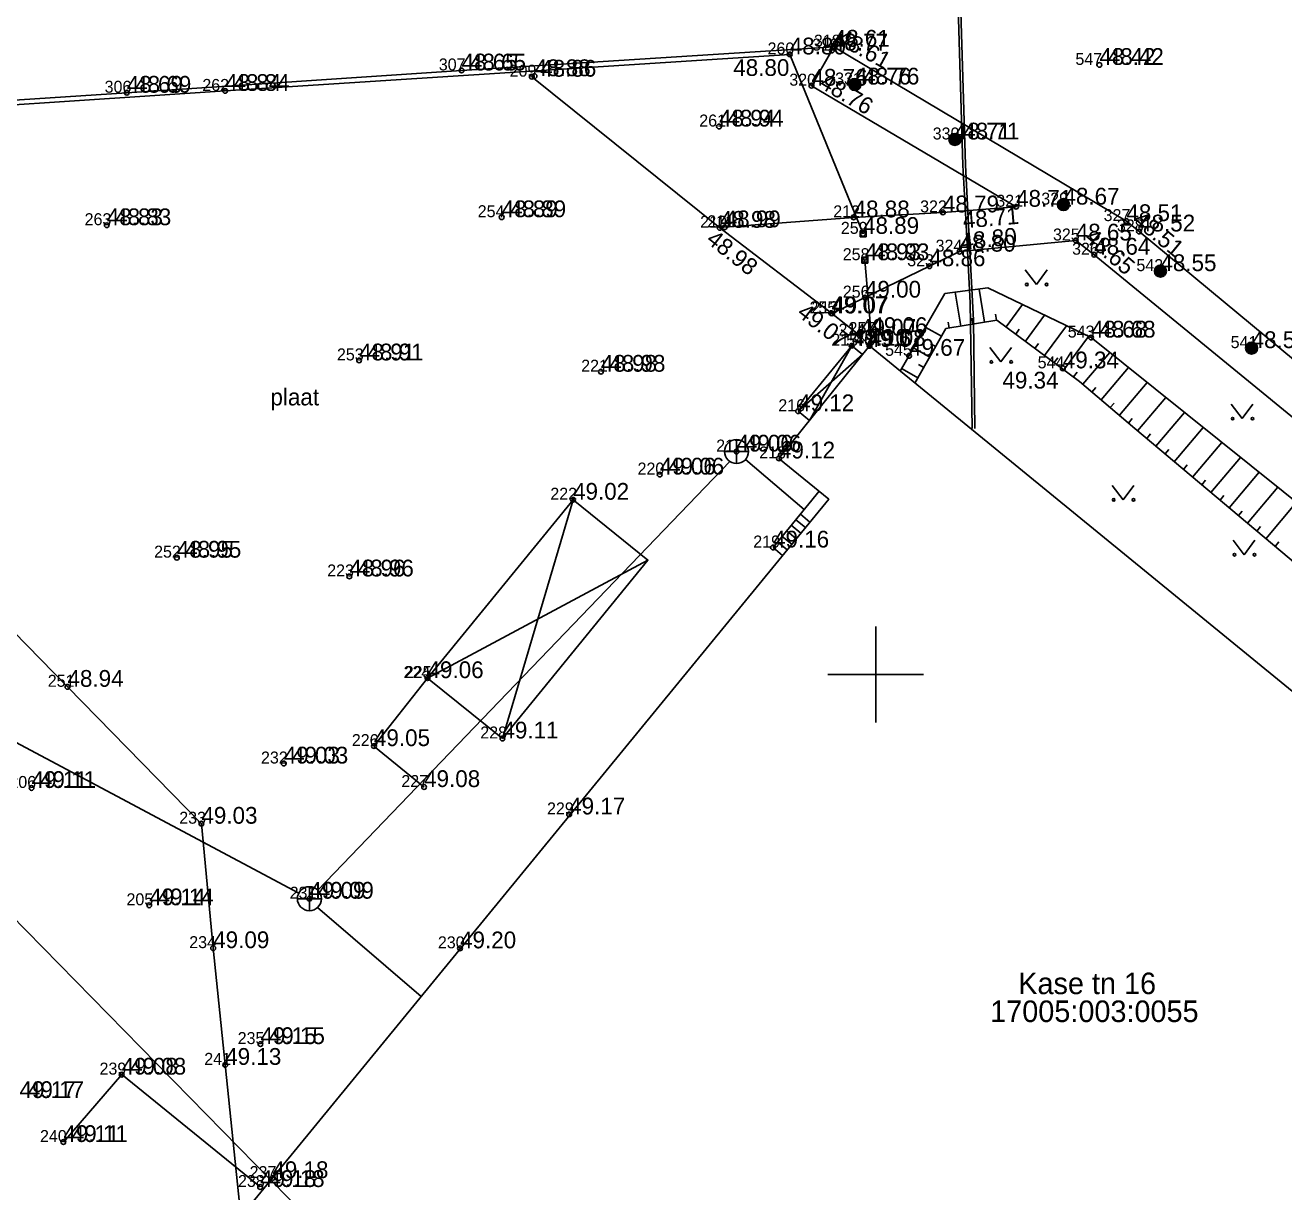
# Model space of a CAD drawing. Extents: x 640876 to 641418, y 6455595 to 6456085.
# Drawn here: x 641114.5 to 641167, y 6455928.4 to 6455977.1 of the extents above; entities that cross this region are included whole.
import ezdxf

# ---------------------------------------------------------------- set-up
doc = ezdxf.new("R2010")
doc.units = 0
for name, color, linetype in [('AED', 7, 'Continuous'), ('HALJASTUS', 7, 'Continuous'), ('HOONE', 7, 'Continuous'), ('HOONEDET', 7, 'Continuous'), ('KKAEV', 7, 'Continuous'), ('KORGUS', 7, 'Continuous'), ('KTRASS', 7, 'Continuous'), ('MOOTKORG', 7, 'Continuous'), ('MOOTMPUNKT', 7, 'Continuous'), ('MOOTNR', 7, 'Continuous'), ('MPKAABEL', 7, 'Continuous'), ('PIIR', 7, 'Continuous'), ('RAJATIS', 7, 'Continuous'), ('RELJEEF', 7, 'Continuous'), ('TEE', 7, 'Continuous'), ('VORK', 7, 'Continuous')]:
    doc.layers.add(name, color=color, linetype=linetype)

msp = doc.modelspace()

# ---------------------------------------------------------------- linework, layer by layer
at = {"layer": 'AED'}
for p, q in [((641149.345, 6455968.521), (641149.345, 6455968.271)), ((641149.345, 6455968.521), (641149.595, 6455968.521)), ((641149.345, 6455968.271), (641149.595, 6455968.271)), ((641149.595, 6455968.521), (641149.595, 6455968.271)), ((641149.424, 6455967.422), (641149.424, 6455967.172)), ((641149.424, 6455967.422), (641149.674, 6455967.422)), ((641149.424, 6455967.172), (641149.674, 6455967.172)), ((641149.674, 6455967.422), (641149.674, 6455967.172))]:
    msp.add_line(p, q, dxfattribs=at)
for points in [[(641149.47, 6455968.396), (641146.41, 6455975.887), (641122.837, 6455974.363), (641106.897, 6455973.309), (641093.89, 6455972.505), (641088.371, 6455978.142)], [(641149.742, 6455963.717), (641149.817, 6455964.213), (641149.549, 6455967.297)], [(641131.288, 6455949.849), (641129.051, 6455947.011), (641131.145, 6455945.301)], [(641124.299, 6455928.604), (641118.519, 6455933.296), (641116.084, 6455930.482)]]:
    msp.add_lwpolyline(points, dxfattribs=at)
at = {"layer": 'HALJASTUS'}
for p, q in [((641156.245, 6455966.89), (641156.709, 6455966.283)), ((641156.709, 6455966.283), (641157.154, 6455966.89)), ((641154.766, 6455963.656), (641155.23, 6455963.049)), ((641155.23, 6455963.049), (641155.675, 6455963.656)), ((641164.841, 6455961.288), (641165.304, 6455960.681)), ((641165.304, 6455960.681), (641165.75, 6455961.288)), ((641159.873, 6455957.895), (641160.336, 6455957.288)), ((641160.336, 6455957.288), (641160.782, 6455957.895)), ((641164.92, 6455955.607), (641165.383, 6455955)), ((641165.383, 6455955), (641165.829, 6455955.607))]:
    msp.add_line(p, q, dxfattribs=at)
for centre in [(641156.308, 6455966.283), (641157.136, 6455966.283), (641154.829, 6455963.049), (641155.657, 6455963.049), (641164.903, 6455960.681), (641165.732, 6455960.681), (641159.935, 6455957.288), (641160.764, 6455957.288), (641164.982, 6455955), (641165.811, 6455955)]:
    msp.add_circle(centre, 0.055, dxfattribs=at)
at = {"layer": 'HOONE'}
for p, q in [((641149.452, 6455963.357), (641148.998, 6455963.723)), ((641147.238, 6455960.606), (641146.76, 6455960.991))]:
    msp.add_line(p, q, dxfattribs=at)
for points in [[(641119.462, 6455922.449), (641148.038, 6455957.319), (641145.961, 6455959.02), (641149.742, 6455963.717)], [(641146.76, 6455960.991), (641148.998, 6455963.723)], [(641149.742, 6455963.717), (641189.36, 6455931.349)], [(641131.288, 6455949.849), (641140.492, 6455954.775), (641137.364, 6455957.296), (641131.288, 6455949.849), (641134.415, 6455947.328)], [(641140.492, 6455954.775), (641134.415, 6455947.328), (641137.364, 6455957.296)]]:
    msp.add_lwpolyline(points, dxfattribs=at)
at = {"layer": 'HOONEDET'}
for p, q in [((641147.637, 6455957.647), (641145.714, 6455955.301)), ((641147.256, 6455956.365), (641146.855, 6455956.693)), ((641146.685, 6455955.669), (641146.284, 6455955.997)), ((641146.875, 6455955.901), (641146.474, 6455956.229)), ((641147.065, 6455956.133), (641146.665, 6455956.461)), ((641146.305, 6455955.204), (641145.904, 6455955.533)), ((641146.495, 6455955.437), (641146.094, 6455955.765)), ((641146.115, 6455954.972), (641145.714, 6455955.301))]:
    msp.add_line(p, q, dxfattribs=at)
for points in [[(641146.76, 6455960.991), (641149.452, 6455963.357)], [(641148.998, 6455963.723), (641147.238, 6455960.606)]]:
    msp.add_lwpolyline(points, dxfattribs=at)
at = {"layer": 'KKAEV'}
for p, q in [((641144.191, 6455958.807), (641144.191, 6455959.807)), ((641143.691, 6455959.307), (641144.691, 6455959.307)), ((641126.355, 6455940.14), (641126.355, 6455941.14)), ((641125.855, 6455940.64), (641126.855, 6455940.64))]:
    msp.add_line(p, q, dxfattribs=at)
for centre in [(641144.191, 6455959.307), (641126.355, 6455940.64)]:
    msp.add_circle(centre, 0.5, dxfattribs=at)
at = {"layer": 'KORGUS'}
for centre in [(641146.41, 6455975.887), (641148.246, 6455976.21), (641159.338, 6455975.449), (641132.709, 6455975.218), (641135.642, 6455974.958), (641118.732, 6455974.289), (641122.837, 6455974.363), (641147.318, 6455974.582), (641149.131, 6455974.631), (641143.459, 6455972.877), (641153.305, 6455972.336), (641155.86, 6455969.527), (641134.384, 6455969.091), (641117.897, 6455968.757), (641143.492, 6455968.649), (641160.465, 6455968.928), (641158.352, 6455968.119), (641153.501, 6455967.653), (641149.549, 6455967.297), (641148.148, 6455965.083), (641158.993, 6455964.066), (641151.393, 6455963.305), (641128.431, 6455963.113), (641157.811, 6455962.781), (641138.528, 6455962.641), (641144.191, 6455959.307), (641140.982, 6455958.347), (641120.822, 6455954.878), (641128.024, 6455954.094), (641125.286, 6455946.284), (641114.756, 6455945.263), (641126.355, 6455940.64), (641119.67, 6455940.365), (641124.312, 6455934.571), (641118.519, 6455933.296), (641116.084, 6455930.482), (641124.299, 6455928.604)]:
    msp.add_circle(centre, 0.1, dxfattribs=at)
at = {"layer": 'KTRASS'}
for points in [[(641126.705, 6455940.99), (641143.906, 6455958.896)], [(641144.564, 6455958.974), (641147.015, 6455956.889)], [(641107.541, 6455950.658), (641125.909, 6455940.865)], [(641126.693, 6455940.271), (641131.028, 6455936.563)]]:
    msp.add_lwpolyline(points, dxfattribs=at)
at = {"layer": 'MOOTMPUNKT'}
for centre in [(641146.41, 6455975.887), (641148.17, 6455976.048), (641148.246, 6455976.21), (641159.338, 6455975.449), (641132.709, 6455975.218), (641135.642, 6455974.958), (641135.757, 6455974.98), (641118.732, 6455974.289), (641122.837, 6455974.363), (641147.318, 6455974.582), (641149.131, 6455974.631), (641143.459, 6455972.877), (641153.305, 6455972.336), (641155.86, 6455969.527), (641157.838, 6455969.617), (641134.384, 6455969.091), (641149.077, 6455969.085), (641152.805, 6455969.293), (641117.897, 6455968.757), (641143.492, 6455968.649), (641143.695, 6455968.671), (641160.465, 6455968.928), (641160.995, 6455968.496), (641149.47, 6455968.396), (641158.352, 6455968.119), (641153.501, 6455967.653), (641159.124, 6455967.526), (641149.549, 6455967.297), (641152.24, 6455967.045), (641161.885, 6455966.84), (641149.551, 6455965.734), (641148.148, 6455965.083), (641148.186, 6455965.074), (641148.998, 6455963.723), (641149.347, 6455964.145), (641149.817, 6455964.213), (641158.993, 6455964.066), (641149.742, 6455963.717), (641151.393, 6455963.305), (641165.694, 6455963.626), (641128.431, 6455963.113), (641157.811, 6455962.781), (641138.528, 6455962.641), (641146.76, 6455960.991), (641144.191, 6455959.307), (641145.961, 6455959.02), (641140.982, 6455958.347), (641137.364, 6455957.296), (641120.822, 6455954.878), (641145.714, 6455955.301), (641128.024, 6455954.094), (641131.288, 6455949.849), (641131.288, 6455949.849), (641116.257, 6455949.486), (641129.051, 6455947.011), (641134.415, 6455947.328), (641125.286, 6455946.284), (641114.756, 6455945.263), (641131.145, 6455945.301), (641121.847, 6455943.77), (641137.202, 6455944.159), (641126.355, 6455940.64), (641119.67, 6455940.365), (641122.34, 6455938.576), (641132.646, 6455938.568), (641124.312, 6455934.571), (641118.519, 6455933.296), (641122.842, 6455933.704), (641116.084, 6455930.482), (641124.299, 6455928.604), (641124.81, 6455928.975)]:
    msp.add_circle(centre, 0.1, dxfattribs=at)
at = {"layer": 'MPKAABEL'}
for points in [[(641081.282, 6455986.001), (641083.826, 6455989.191), (641093.656, 6455990.177), (641101.434, 6455990.689), (641109.211, 6455991.201), (641116.735, 6455992.286), (641117.253, 6455992.438), (641137.02, 6455993.508), (641152.446, 6455994.375), (641152.745, 6455994.399), (641153.077, 6455993.956), (641153.192, 6455989.529), (641153.743, 6455971.272), (641153.877, 6455968.765), (641154.087, 6455964.787), (641154.134, 6455960.265)], [(641154.034, 6455960.264), (641153.95, 6455965.518), (641153.778, 6455968.761), (641153.643, 6455971.268), (641153.102, 6455989.126), (641152.978, 6455993.905), (641152.599, 6455994.224), (641152.147, 6455994.252), (641142.791, 6455993.73), (641131.26, 6455993.087), (641117.217, 6455992.367), (641116.76, 6455992.188), (641112.991, 6455991.645), (641109.221, 6455991.101), (641101.443, 6455990.589), (641093.665, 6455990.077), (641088.757, 6455989.569), (641083.848, 6455989.06), (641081.36, 6455985.939)]]:
    msp.add_lwpolyline(points, dxfattribs=at)
at = {"layer": 'PIIR'}
for points in [[(641222.58, 6455998.61), (641237.36, 6455995.24), (641235.34, 6455991.29), (641228.11, 6455971.68), (641220.5, 6455953.19), (641213.41, 6455936.25), (641201.58, 6455908.74), (641224.93, 6455905.88), (641191.87, 6455860.58), (641157.02, 6455885.66), (641160.91, 6455891.99), (641102.26, 6455951.82), (641074.95, 6455979.64), (641084.84, 6455991.92)], [(641098.62, 6455818.85), (641093.41, 6455823.22), (641084.65, 6455830.08), (641067.32, 6455843.61), (641055.55, 6455852.8), (641061.31, 6455859.9), (641051.68, 6455867.61), (641067, 6455888.54), (641060.97, 6455894.57), (641075.14, 6455914.24), (641087.11, 6455930.82), (641102.26, 6455951.82), (641160.91, 6455891.99), (641157.02, 6455885.66), (641139.49, 6455869), (641124.05, 6455849.81)]]:
    msp.add_lwpolyline(points, close=True, dxfattribs=at)
at = {"layer": 'RAJATIS'}
for centre, radius in [((641149.131, 6455974.631), 0.25), ((641149.131, 6455974.631), 0.225), ((641149.131, 6455974.631), 0.2), ((641149.131, 6455974.631), 0.175), ((641149.131, 6455974.631), 0.15), ((641149.131, 6455974.631), 0.125), ((641149.131, 6455974.631), 0.1), ((641149.131, 6455974.631), 0.075), ((641149.131, 6455974.631), 0.05), ((641149.131, 6455974.631), 0.025), ((641153.305, 6455972.336), 0.25), ((641153.305, 6455972.336), 0.225), ((641153.305, 6455972.336), 0.2), ((641153.305, 6455972.336), 0.175), ((641153.305, 6455972.336), 0.15), ((641153.305, 6455972.336), 0.125), ((641153.305, 6455972.336), 0.1), ((641153.305, 6455972.336), 0.075), ((641153.305, 6455972.336), 0.05), ((641153.305, 6455972.336), 0.025), ((641157.838, 6455969.617), 0.25), ((641157.838, 6455969.617), 0.225), ((641157.838, 6455969.617), 0.2), ((641157.838, 6455969.617), 0.175), ((641157.838, 6455969.617), 0.15), ((641157.838, 6455969.617), 0.125), ((641157.838, 6455969.617), 0.1), ((641157.838, 6455969.617), 0.075), ((641157.838, 6455969.617), 0.05), ((641157.838, 6455969.617), 0.025), ((641161.885, 6455966.84), 0.25), ((641161.885, 6455966.84), 0.225), ((641161.885, 6455966.84), 0.2), ((641161.885, 6455966.84), 0.175), ((641161.885, 6455966.84), 0.15), ((641161.885, 6455966.84), 0.125), ((641161.885, 6455966.84), 0.1), ((641161.885, 6455966.84), 0.075), ((641161.885, 6455966.84), 0.05), ((641161.885, 6455966.84), 0.025), ((641165.694, 6455963.626), 0.25), ((641165.694, 6455963.626), 0.225), ((641165.694, 6455963.626), 0.2), ((641165.694, 6455963.626), 0.175), ((641165.694, 6455963.626), 0.15), ((641165.694, 6455963.626), 0.125), ((641165.694, 6455963.626), 0.1), ((641165.694, 6455963.626), 0.075), ((641165.694, 6455963.626), 0.05), ((641165.694, 6455963.626), 0.025)]:
    msp.add_circle(centre, radius, dxfattribs=at)
at = {"layer": 'RELJEEF'}
for p, q in [((641153.559, 6455964.543), (641153.321, 6455965.959)), ((641154.545, 6455964.709), (641154.313, 6455966.09)), ((641155.443, 6455964.508), (641156.134, 6455965.441)), ((641154.052, 6455964.626), (641154.011, 6455964.873)), ((641155.038, 6455964.792), (641154.997, 6455965.038)), ((641156.247, 6455963.913), (641157.051, 6455964.999)), ((641152.751, 6455964.122), (641152.099, 6455964.493)), ((641153.066, 6455964.461), (641153.024, 6455964.707)), ((641155.845, 6455964.21), (641155.994, 6455964.411)), ((641157.051, 6455963.318), (641157.969, 6455964.558)), ((641157.854, 6455962.723), (641158.886, 6455964.117)), ((641152.257, 6455963.253), (641151.605, 6455963.624)), ((641152.504, 6455963.688), (641152.287, 6455963.811)), ((641156.649, 6455963.615), (641156.798, 6455963.816)), ((641158.65, 6455962.118), (641159.776, 6455963.438)), ((641152.01, 6455962.818), (641151.793, 6455962.942)), ((641157.453, 6455963.02), (641157.601, 6455963.221)), ((641159.411, 6455961.469), (641160.557, 6455962.812)), ((641151.763, 6455962.384), (641151.111, 6455962.754)), ((641158.256, 6455962.425), (641158.405, 6455962.626)), ((641159.03, 6455961.793), (641159.193, 6455961.983)), ((641160.172, 6455960.82), (641161.337, 6455962.186)), ((641159.791, 6455961.144), (641159.953, 6455961.334)), ((641160.933, 6455960.172), (641162.107, 6455961.569)), ((641160.552, 6455960.495), (641160.714, 6455960.685)), ((641161.699, 6455959.528), (641162.887, 6455960.943)), ((641162.464, 6455958.885), (641163.668, 6455960.317)), ((641161.316, 6455959.85), (641161.477, 6455960.041)), ((641163.23, 6455958.242), (641164.448, 6455959.691)), ((641162.082, 6455959.207), (641162.242, 6455959.398)), ((641162.847, 6455958.563), (641163.008, 6455958.755)), ((641163.996, 6455957.598), (641165.229, 6455959.066)), ((641163.613, 6455957.92), (641163.774, 6455958.111)), ((641164.761, 6455956.955), (641166.009, 6455958.44)), ((641165.527, 6455956.312), (641166.789, 6455957.814)), ((641164.378, 6455957.277), (641164.539, 6455957.468)), ((641166.292, 6455955.669), (641167.57, 6455957.189)), ((641165.144, 6455956.633), (641165.305, 6455956.825)), ((641165.91, 6455955.99), (641166.07, 6455956.182)), ((641166.675, 6455955.347), (641166.836, 6455955.538))]:
    msp.add_line(p, q, dxfattribs=at)
for points in [[(641151.026, 6455962.667), (641152.889, 6455965.903), (641154.684, 6455966.138), (641158.993, 6455964.066), (641177.637, 6455949.117), (641191.912, 6455936.582), (641192.954, 6455935.439), (641193.346, 6455934.637), (641193.426, 6455931.281), (641192.589, 6455929.191), (641189.209, 6455924.627), (641185.194, 6455919.704), (641183.118, 6455916.876)], [(641151.64, 6455962.166), (641152.931, 6455964.438), (641155.056, 6455964.795), (641158.507, 6455962.239), (641160.822, 6455960.264), (641191.133, 6455934.798)]]:
    msp.add_lwpolyline(points, dxfattribs=at)
at = {"layer": 'TEE'}
for points in [[(641219.562, 6455985.852), (641216.822, 6455976.794), (641214.309, 6455968.346), (641210.175, 6455958.541), (641206.979, 6455950.86), (641202.453, 6455940.169), (641200.572, 6455935.729), (641195.267, 6455940.101), (641183.381, 6455949.957), (641172.174, 6455959.233), (641160.995, 6455968.496)], [(641088.438, 6455978.34), (641093.974, 6455972.705), (641102.503, 6455973.228), (641118.732, 6455974.289), (641132.709, 6455975.218), (641148.246, 6455976.21), (641160.465, 6455968.928), (641160.995, 6455968.496)], [(641148.17, 6455976.048), (641147.318, 6455974.582), (641155.86, 6455969.527), (641152.805, 6455969.293), (641149.077, 6455969.085)], [(641135.642, 6455974.958), (641143.492, 6455968.649), (641148.148, 6455965.083), (641149.347, 6455964.145), (641149.742, 6455963.717)], [(641123.495, 6455927.37), (641122.34, 6455938.576), (641121.847, 6455943.77), (641116.257, 6455949.486), (641107.796, 6455958.136), (641098.01, 6455968.023), (641093.89, 6455972.505)], [(641143.484, 6455968.655), (641149.077, 6455969.085)], [(641149.551, 6455965.734), (641152.24, 6455967.045), (641153.501, 6455967.653), (641158.352, 6455968.119), (641159.124, 6455967.526), (641170.932, 6455957.845)], [(641148.186, 6455965.074), (641149.551, 6455965.734)]]:
    msp.add_lwpolyline(points, dxfattribs=at)
at = {"layer": 'VORK'}
for p, q in [((641150, 6455952), (641150, 6455948)), ((641148, 6455950), (641152, 6455950))]:
    msp.add_line(p, q, dxfattribs=at)

# ---------------------------------------------------------------- texts
at = {"layer": 'KORGUS'}
for s, rotation, p in [('48.61', 331.5359, (641148.318, 6455976.371)), ('48.76', 329.4133, (641147.605, 6455974.532)), ('48.71', 4.7785, (641153.665, 6455968.621)), ('48.51', 320.3826, (641160.69, 6455968.883)), ('48.80', 6.0406, (641153.602, 6455967.721)), ('48.98', 321.6919, (641142.88, 6455968.067)), ('48.65', 319.3834, (641158.661, 6455968.155)), ('49.07', 322.4862, (641146.673, 6455965.005))]:
    msp.add_text(s, height=0.7, rotation=rotation, dxfattribs=at).set_placement(p)
for s, p in [('48.65', (641133.059, 6455975.218)), ('48.42', (641159.688, 6455975.449)), ('48.86', (641135.992, 6455974.958)), ('48.80', (641144.053, 6455974.989)), ('48.69', (641119.082, 6455974.289)), ('48.84', (641123.187, 6455974.363)), ('48.76', (641149.481, 6455974.631)), ('48.94', (641143.809, 6455972.877)), ('48.71', (641153.655, 6455972.336)), ('48.89', (641134.734, 6455969.091)), ('48.83', (641118.247, 6455968.757)), ('48.93', (641149.899, 6455967.297)), ('49.67', (641149.658, 6455963.675)), ('48.68', (641159.343, 6455964.066)), ('48.91', (641128.781, 6455963.113)), ('48.98', (641138.878, 6455962.641)), ('49.34', (641155.29, 6455961.938)), ('49.06', (641144.541, 6455959.307)), ('49.06', (641141.332, 6455958.347)), ('48.95', (641121.172, 6455954.878)), ('48.96', (641128.374, 6455954.094)), ('49.03', (641125.636, 6455946.284)), ('49.11', (641115.106, 6455945.263)), ('49.09', (641126.705, 6455940.64)), ('49.14', (641120.02, 6455940.365)), ('49.15', (641124.662, 6455934.571)), ('49.08', (641118.869, 6455933.296)), ('49.17', (641114.604, 6455932.318)), ('49.11', (641116.434, 6455930.482)), ('49.18', (641124.649, 6455928.604))]:
    msp.add_text(s, height=0.7, dxfattribs=at).set_placement(p)
at = {"layer": 'MOOTKORG'}
for s, p in [('48.80', (641146.41, 6455975.887)), ('48.77', (641148.17, 6455976.048)), ('48.61', (641148.246, 6455976.21)), ('48.65', (641132.709, 6455975.218)), ('48.42', (641159.338, 6455975.449)), ('48.88', (641135.757, 6455974.98)), ('48.69', (641118.732, 6455974.289)), ('48.84', (641122.837, 6455974.363)), ('48.76', (641147.318, 6455974.582)), ('48.76', (641149.131, 6455974.631)), ('48.94', (641143.459, 6455972.877)), ('48.71', (641153.305, 6455972.336)), ('48.71', (641155.86, 6455969.527)), ('48.67', (641157.838, 6455969.617)), ('48.89', (641134.384, 6455969.091)), ('48.88', (641149.077, 6455969.085)), ('48.79', (641152.805, 6455969.293)), ('48.51', (641160.465, 6455968.928)), ('48.83', (641117.897, 6455968.757)), ('48.98', (641143.492, 6455968.649)), ('48.99', (641143.695, 6455968.671)), ('48.89', (641149.47, 6455968.396)), ('48.52', (641160.995, 6455968.496)), ('48.65', (641158.352, 6455968.119)), ('48.80', (641153.501, 6455967.653)), ('48.64', (641159.124, 6455967.526)), ('48.93', (641149.549, 6455967.297)), ('48.86', (641152.24, 6455967.045)), ('48.55', (641161.885, 6455966.84)), ('49.00', (641149.551, 6455965.734)), ('49.07', (641148.148, 6455965.083)), ('49.07', (641148.186, 6455965.074)), ('49.06', (641149.817, 6455964.213)), ('49.10', (641148.998, 6455963.723)), ('49.07', (641149.347, 6455964.145)), ('49.08', (641149.742, 6455963.717)), ('48.68', (641158.993, 6455964.066)), ('48.91', (641128.431, 6455963.113)), ('49.67', (641151.393, 6455963.305)), ('48.54', (641165.694, 6455963.626)), ('48.98', (641138.528, 6455962.641)), ('49.34', (641157.811, 6455962.781)), ('49.12', (641146.76, 6455960.991)), ('49.06', (641144.191, 6455959.307)), ('49.12', (641145.961, 6455959.02)), ('49.06', (641140.982, 6455958.347)), ('49.02', (641137.364, 6455957.296)), ('49.16', (641145.714, 6455955.301)), ('48.95', (641120.822, 6455954.878)), ('48.96', (641128.024, 6455954.094)), ('48.94', (641116.257, 6455949.486)), ('49.06', (641131.288, 6455949.849)), ('49.06', (641131.288, 6455949.849)), ('49.05', (641129.051, 6455947.011)), ('49.11', (641134.415, 6455947.328)), ('49.03', (641125.286, 6455946.284)), ('49.11', (641114.756, 6455945.263)), ('49.08', (641131.145, 6455945.301)), ('49.03', (641121.847, 6455943.77)), ('49.17', (641137.202, 6455944.159)), ('49.09', (641126.355, 6455940.64)), ('49.14', (641119.67, 6455940.365)), ('49.09', (641122.34, 6455938.576)), ('49.20', (641132.646, 6455938.568)), ('49.15', (641124.312, 6455934.571)), ('49.13', (641122.842, 6455933.704)), ('49.08', (641118.519, 6455933.296)), ('49.17', (641114.254, 6455932.318)), ('49.11', (641116.084, 6455930.482)), ('49.18', (641124.81, 6455928.975)), ('49.18', (641124.299, 6455928.604))]:
    msp.add_text(s, height=0.7, dxfattribs=at).set_placement(p)
at = {"layer": 'MOOTNR'}
for s, p in [('319', (641147.345, 6455976.048)), ('318', (641147.421, 6455976.21)), ('260', (641145.485, 6455975.887)), ('547', (641158.338, 6455975.449)), ('307', (641131.759, 6455975.218)), ('209', (641134.717, 6455974.958)), ('262', (641121.887, 6455974.363)), ('320', (641146.393, 6455974.582)), ('331', (641148.306, 6455974.631)), ('306', (641117.807, 6455974.289)), ('261', (641142.634, 6455972.877)), ('330', (641152.38, 6455972.336)), ('322', (641151.855, 6455969.293)), ('321', (641155.035, 6455969.527)), ('329', (641156.913, 6455969.617)), ('263', (641116.972, 6455968.757)), ('254', (641133.384, 6455969.091)), ('210', (641142.668, 6455968.649)), ('211', (641142.97, 6455968.671)), ('212', (641148.227, 6455969.085)), ('327', (641159.515, 6455968.928)), ('259', (641148.545, 6455968.396)), ('325', (641157.402, 6455968.119)), ('328', (641160.07, 6455968.496)), ('324', (641152.501, 6455967.653)), ('326', (641158.199, 6455967.526)), ('258', (641148.624, 6455967.297)), ('323', (641151.315, 6455967.045)), ('542', (641160.885, 6455966.84)), ('256', (641148.626, 6455965.734)), ('255', (641147.236, 6455965.074)), ('213', (641147.323, 6455965.083)), ('214', (641148.447, 6455964.145)), ('257', (641148.867, 6455964.213)), ('543', (641158.018, 6455964.066)), ('215', (641148.148, 6455963.723)), ('546', (641148.767, 6455963.717)), ('541', (641164.819, 6455963.626)), ('253', (641127.506, 6455963.113)), ('545', (641150.393, 6455963.305)), ('221', (641137.703, 6455962.641)), ('544', (641156.761, 6455962.781)), ('216', (641145.935, 6455960.991)), ('217', (641143.341, 6455959.307)), ('218', (641145.136, 6455959.02)), ('220', (641140.057, 6455958.347)), ('222', (641136.415, 6455957.296)), ('219', (641144.889, 6455955.301)), ('252', (641119.872, 6455954.878)), ('223', (641127.099, 6455954.094)), ('224', (641130.288, 6455949.849)), ('225', (641130.338, 6455949.849)), ('251', (641115.432, 6455949.486)), ('228', (641133.49, 6455947.328)), ('226', (641128.127, 6455947.011)), ('232', (641124.336, 6455946.284)), ('206', (641113.831, 6455945.263)), ('227', (641130.195, 6455945.301)), ('229', (641136.277, 6455944.159)), ('233', (641120.922, 6455943.77)), ('205', (641118.72, 6455940.365)), ('231', (641125.531, 6455940.64)), ('234', (641121.34, 6455938.576)), ('230', (641131.721, 6455938.568)), ('235', (641123.362, 6455934.571)), ('241', (641121.967, 6455933.704)), ('239', (641117.594, 6455933.296)), ('240', (641115.109, 6455930.482)), ('237', (641123.86, 6455928.975)), ('238', (641123.374, 6455928.604))]:
    msp.add_text(s, height=0.5, dxfattribs=at).set_placement(p)
at = {"layer": 'PIIR'}
for s, p in [('Kase tn 16', (641155.951, 6455936.655)), ('17005:003:0055', (641154.78, 6455935.49))]:
    msp.add_text(s, height=0.9, dxfattribs=at).set_placement(p)
at = {"layer": 'TEE'}
msp.add_text('plaat', height=0.7, dxfattribs=at).set_placement((641124.73, 6455961.234))

doc.saveas('drawing.dxf')
